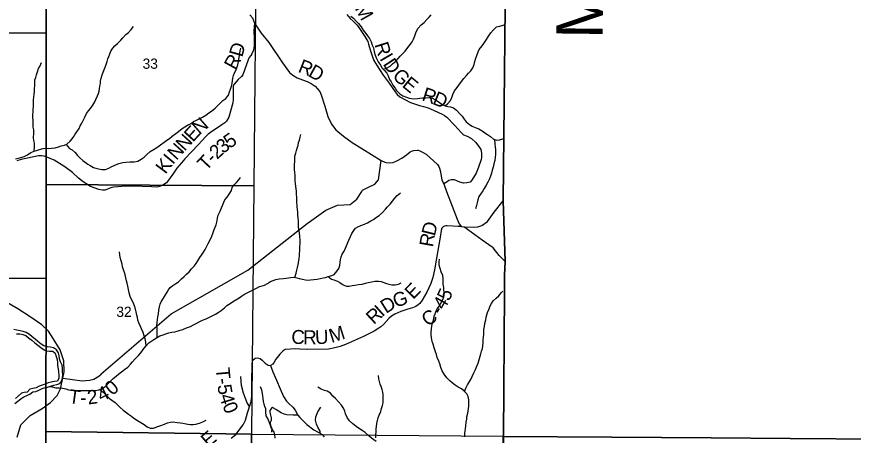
# Model space of a CAD drawing. Extents: x 2043100 to 2470832, y 443715 to 810583.
# Drawn here: x 2290243 to 2308244, y 624120 to 633122 of the extents above; entities that cross this region are included whole.
import ezdxf

# ---------------------------------------------------------------- set-up
doc = ezdxf.new("R2010")
doc.units = 0
for name, color, linetype in [('GM_X_Adjacent_County', 7, 'Continuous'), ('GM_X_Adjacent_County_Text', 7, 'Continuous'), ('GM_X_County', 7, 'Continuous'), ('GM_X_County_Road', 7, 'Continuous'), ('GM_X_County_Road_Text', 7, 'Continuous'), ('GM_X_Major_River', 7, 'Continuous'), ('GM_X_Minor_River', 7, 'Continuous'), ('GM_X_Section', 7, 'Continuous'), ('GM_X_Section_Text', 7, 'Continuous'), ('GM_X_State_Route', 7, 'Continuous'), ('GM_X_Township', 7, 'Continuous'), ('GM_X_Township_Road', 7, 'Continuous'), ('GM_X_Township_Road_Text', 7, 'Continuous'), ('GM_X_Township_ROW', 7, 'Continuous')]:
    doc.layers.add(name, color=color, linetype=linetype)

msp = doc.modelspace()

# ---------------------------------------------------------------- linework, layer by layer
at = {"layer": 'GM_X_Adjacent_County'}
msp.add_lwpolyline([(2310832, 624022), (2306890, 624048), (2305185, 624062), (2303048, 624077), (2300717, 624094), (2300736, 627208), (2300738, 627560), (2300751, 627857), (2300714, 629163), (2300774, 635425)], dxfattribs=at)
at = {"layer": 'GM_X_County'}
msp.add_lwpolyline([(2300774, 635425), (2300714, 629163), (2300751, 627857), (2300738, 627560), (2300736, 627208), (2300717, 624094), (2303048, 624077), (2305185, 624062), (2306890, 624048), (2310832, 624022)], dxfattribs=at)
at = {"layer": 'GM_X_County_Road'}
for points in [[(2295261, 633166), (2295315, 633098), (2295360, 632984), (2295505, 632772), (2295668, 632569), (2295965, 632129), (2296113, 631925), (2296182, 631862), (2296276, 631806), (2296395, 631762), (2296495, 631730), (2296579, 631689), (2296662, 631632), (2296763, 631513), (2296796, 631445), (2296874, 631199), (2296938, 630976), (2297016, 630814), (2297109, 630692), (2297276, 630552), (2297464, 630417), (2298082, 630029), (2298162, 629993), (2298196, 629986), (2298273, 629982), (2298342, 629990), (2298434, 630029), (2298531, 630078), (2298627, 630151), (2298706, 630219), (2298736, 630232), (2298790, 630245), (2298865, 630251), (2298879, 630250), (2298917, 630238), (2298976, 630211), (2299052, 630167), (2299295, 629943), (2299323, 629901), (2299341, 629864), (2299360, 629787), (2299392, 629607), (2299433, 629530), (2299494, 629364), (2299614, 629046), (2299720, 628767), (2299763, 628667), (2299790, 628631), (2299808, 628610), (2299866, 628605), (2300082, 628594), (2300168, 628603), (2300252, 628632), (2300371, 628721), (2300519, 628917), (2300714, 629163)], [(2297345, 633167), (2297418, 633081), (2297482, 633026), (2297535, 632980), (2297571, 632944), (2297608, 632889), (2297731, 632695), (2297776, 632622), (2297797, 632588), (2297815, 632534), (2297848, 632410), (2297898, 632258), (2297929, 632182), (2297998, 632069), (2298126, 631868), (2298255, 631694), (2298385, 631505), (2298428, 631450), (2298488, 631398), (2298716, 631278), (2298908, 631216), (2298996, 631194), (2299097, 631163), (2299225, 631108), (2299400, 631026), (2299450, 630996), (2299499, 630963), (2299666, 630790), (2299745, 630702), (2299804, 630635), (2299860, 630585), (2299937, 630552), (2300029, 630505), (2300120, 630417), (2300201, 630312), (2300230, 630266), (2300246, 630188), (2300241, 630096), (2300234, 630052), (2300179, 629889), (2300127, 629756), (2300040, 629605), (2299997, 629563), (2299931, 629546), (2299855, 629542), (2299777, 629561), (2299728, 629586), (2299662, 629614), (2299598, 629613), (2299540, 629599), (2299506, 629572), (2299433, 629530)], [(2299808, 628610), (2299740, 628607), (2299504, 628623), (2299478, 628625), (2299448, 628614), (2299420, 628600), (2299394, 628574), (2299379, 628527), (2299352, 628383), (2299271, 627889), (2299233, 627681), (2299195, 627510), (2299154, 627383), (2299068, 627194), (2298967, 627023), (2298916, 626954), (2298882, 626922), (2298829, 626890), (2298759, 626859), (2298659, 626832), (2298506, 626782), (2298376, 626727), (2298307, 626684), (2298253, 626634), (2298140, 626509), (2298079, 626452), (2298037, 626420), (2297938, 626359), (2297707, 626242), (2297315, 626070), (2297203, 626031), (2297089, 625998), (2296954, 625973), (2296506, 625961), (2296336, 625969), (2296241, 625982), (2296022, 625962), (2295976, 625938), (2295905, 625867), (2295820, 625758), (2295780, 625690), (2295753, 625651), (2295705, 625623), (2295756, 625481), (2295836, 625304), (2295910, 625116), (2295982, 624956), (2296045, 624855), (2296109, 624795), (2296184, 624726), (2296236, 624658), (2296294, 624550), (2296336, 624505), (2296391, 624443), (2296488, 624352), (2296637, 624237), (2296727, 624188), (2296773, 624165), (2296816, 624138), (2296860, 624089)]]:
    msp.add_lwpolyline(points, dxfattribs=at)
at = {"layer": 'GM_X_Major_River'}
for points in [[(2290200, 624803), (2290269, 624853), (2290333, 624904), (2290396, 624947), (2290462, 624978), (2290523, 625000), (2290589, 625051), (2290656, 625064), (2290708, 625084), (2290776, 625121), (2290837, 625138), (2290905, 625154), (2290973, 625173), (2291041, 625198), (2291104, 625211), (2291168, 625235), (2291214, 625288), (2291231, 625352), (2291236, 625422), (2291225, 625496), (2291226, 625564), (2291220, 625628), (2291187, 625700), (2291164, 625764), (2291160, 625826), (2291143, 625892), (2291100, 625958), (2291038, 626003), (2290972, 626012), (2290902, 626022), (2290830, 626045), (2290767, 626078), (2290697, 626134), (2290640, 626187), (2290576, 626240), (2290515, 626290), (2290449, 626333), (2290385, 626353), (2290315, 626366), (2290248, 626383), (2290184, 626398)], [(2290239, 626299), (2290307, 626302), (2290375, 626288), (2290438, 626267), (2290498, 626212), (2290567, 626162), (2290635, 626111), (2290696, 626057), (2290762, 626008), (2290831, 625955), (2290881, 625939), (2290947, 625930), (2291019, 625931), (2291073, 625889), (2291094, 625817), (2291111, 625749), (2291119, 625681), (2291122, 625617), (2291135, 625551), (2291145, 625483), (2291152, 625411), (2291147, 625347), (2291118, 625285), (2291056, 625276), (2290986, 625261), (2290920, 625249), (2290853, 625222), (2290725, 625177), (2290658, 625142), (2290592, 625123), (2290524, 625110), (2290471, 625048), (2290403, 625043), (2290343, 625026), (2290282, 624970), (2290217, 624909)]]:
    msp.add_lwpolyline(points, dxfattribs=at)
at = {"layer": 'GM_X_Minor_River'}
for points in [[(2297436, 633135), (2297488, 633090), (2297548, 633026), (2297601, 632980), (2297655, 632908), (2297697, 632835), (2297758, 632763), (2297792, 632711), (2297835, 632651), (2297867, 632579), (2297894, 632514), (2297918, 632452), (2297938, 632368), (2297955, 632298), (2297987, 632226), (2298022, 632152), (2298068, 632080), (2298105, 632016), (2298155, 631969), (2298205, 631907), (2298234, 631849), (2298266, 631773), (2298299, 631719), (2298335, 631653), (2298384, 631584), (2298416, 631532), (2298486, 631466), (2298555, 631418), (2298627, 631389), (2298687, 631373), (2298739, 631364), (2298801, 631356), (2298867, 631362), (2298921, 631373), (2298976, 631379), (2299044, 631380), (2299120, 631384), (2299190, 631371), (2299241, 631341), (2299291, 631313), (2299341, 631279), (2299393, 631244), (2299461, 631204), (2299517, 631192), (2299577, 631187), (2299645, 631161), (2299706, 631112), (2299778, 631036), (2299828, 630984), (2299875, 630922), (2299917, 630861), (2299984, 630803), (2300042, 630767), (2300110, 630740), (2300190, 630714), (2300262, 630669), (2300315, 630627), (2300377, 630589), (2300435, 630544), (2300505, 630490), (2300571, 630464), (2300635, 630473), (2300703, 630497), (2300731, 630506)], [(2298130, 631993), (2298203, 632019), (2298276, 632061), (2298328, 632110), (2298399, 632168), (2298451, 632221), (2298493, 632271), (2298542, 632322), (2298602, 632380), (2298657, 632460), (2298715, 632531), (2298750, 632585), (2298780, 632639), (2298811, 632710), (2298841, 632794), (2298884, 632874), (2298946, 632949), (2299011, 632997), (2299069, 633060), (2299116, 633112), (2299162, 633162)], [(2299465, 631203), (2299519, 631259), (2299574, 631319), (2299604, 631383), (2299627, 631451), (2299663, 631526), (2299718, 631600), (2299756, 631651), (2299815, 631727), (2299867, 631795), (2299922, 631856), (2299966, 631910), (2300018, 631961), (2300061, 632021), (2300089, 632097), (2300104, 632157), (2300122, 632228), (2300141, 632286), (2300175, 632364), (2300196, 632414), (2300258, 632495), (2300297, 632549), (2300351, 632632), (2300398, 632702), (2300445, 632776), (2300505, 632843), (2300570, 632903), (2300642, 632920), (2300712, 632942), (2300755, 632952)], [(2290219, 630064), (2290275, 630082), (2290329, 630096), (2290403, 630117), (2290475, 630153), (2290546, 630202), (2290618, 630232), (2290672, 630245), (2290732, 630263), (2290809, 630286), (2290873, 630292), (2290935, 630290), (2290995, 630293), (2291067, 630305), (2291143, 630326), (2291203, 630342), (2291268, 630363), (2291320, 630381), (2291396, 630444), (2291437, 630496), (2291469, 630546), (2291499, 630598), (2291534, 630649), (2291586, 630721), (2291609, 630775), (2291645, 630832), (2291682, 630906), (2291708, 630962), (2291743, 631038), (2291787, 631097), (2291828, 631151), (2291878, 631218), (2291925, 631290), (2291947, 631342), (2291978, 631418), (2292000, 631469), (2292020, 631521), (2292025, 631573), (2292035, 631627), (2292045, 631683), (2292048, 631733), (2292060, 631799), (2292083, 631870), (2292116, 631964), (2292148, 632036), (2292170, 632096), (2292191, 632159), (2292205, 632215), (2292222, 632269), (2292248, 632325), (2292277, 632395), (2292311, 632448), (2292357, 632498), (2292412, 632543), (2292486, 632619), (2292523, 632671), (2292591, 632740), (2292650, 632784), (2292708, 632845), (2292757, 632909)], [(2291307, 630376), (2291381, 630289), (2291435, 630256), (2291503, 630204), (2291548, 630138), (2291598, 630090), (2291668, 630027), (2291773, 629951), (2291825, 629922), (2291897, 629880), (2291949, 629862), (2292003, 629851), (2292075, 629837), (2292155, 629838), (2292223, 629862), (2292279, 629890), (2292356, 629931), (2292444, 629966), (2292524, 629984), (2292592, 629997), (2292680, 630001), (2292772, 630004), (2292849, 630012), (2292919, 630057), (2292987, 630103), (2293042, 630156), (2293116, 630224), (2293203, 630275), (2293281, 630321), (2293335, 630366), (2293414, 630424), (2293472, 630467), (2293529, 630505), (2293591, 630554), (2293669, 630612), (2293722, 630653), (2293804, 630719), (2293859, 630756), (2293915, 630788), (2293995, 630827), (2294046, 630865), (2294098, 630893), (2294166, 630924), (2294242, 630964), (2294311, 631005), (2294377, 631053), (2294436, 631092), (2294510, 631158), (2294579, 631217), (2294627, 631273), (2294679, 631318), (2294746, 631364), (2294800, 631434), (2294823, 631505), (2294843, 631567), (2294864, 631629), (2294876, 631689), (2294885, 631751), (2294891, 631803), (2294905, 631860), (2294932, 631912), (2294958, 631962), (2294982, 632020), (2294999, 632090), (2295015, 632161), (2295022, 632211), (2295034, 632285), (2295043, 632341), (2295053, 632391), (2295067, 632443)], [(2290618, 630232), (2290627, 630326), (2290627, 630399), (2290614, 630461), (2290602, 630515), (2290609, 630619), (2290609, 630687), (2290598, 630749), (2290594, 630821), (2290595, 630897), (2290593, 630951), (2290592, 631013), (2290596, 631067), (2290600, 631137), (2290603, 631187), (2290603, 631265), (2290604, 631334), (2290608, 631392), (2290617, 631446), (2290623, 631514), (2290629, 631580), (2290630, 631634), (2290632, 631700), (2290635, 631762), (2290651, 631814), (2290672, 631869), (2290690, 631937), (2290715, 632009), (2290747, 632065), (2290775, 632136)], [(2296226, 627514), (2296255, 627603), (2296273, 627669), (2296286, 627725), (2296302, 627796), (2296317, 627870), (2296323, 627920), (2296329, 627978), (2296330, 628030), (2296334, 628090), (2296337, 628166), (2296343, 628250), (2296346, 628323), (2296334, 628397), (2296325, 628471), (2296317, 628535), (2296310, 628617), (2296308, 628669), (2296303, 628731), (2296299, 628791), (2296294, 628857), (2296290, 628917), (2296286, 628973), (2296281, 629031), (2296268, 629163), (2296268, 629233), (2296263, 629305), (2296261, 629367), (2296255, 629421), (2296248, 629473), (2296240, 629533), (2296235, 629595), (2296233, 629659), (2296232, 629716), (2296228, 629772), (2296222, 629838), (2296217, 629892), (2296217, 629952), (2296226, 630002), (2296230, 630060), (2296230, 630126), (2296249, 630186), (2296267, 630244), (2296280, 630297), (2296298, 630351), (2296308, 630417), (2296325, 630469), (2296341, 630531), (2296360, 630587)], [(2300526, 630482), (2300534, 630390), (2300537, 630318), (2300543, 630268), (2300547, 630214), (2300546, 630156), (2300540, 630104), (2300531, 630028), (2300513, 629955), (2300498, 629885), (2300476, 629823), (2300457, 629757), (2300437, 629693), (2300415, 629634), (2300382, 629562), (2300344, 629496), (2300301, 629427), (2300273, 629377), (2300226, 629305), (2300190, 629252), (2300165, 629186), (2300151, 629116), (2300138, 629062), (2300118, 628992)], [(2293268, 626227), (2293267, 626310), (2293267, 626366), (2293264, 626422), (2293260, 626475), (2293263, 626555), (2293269, 626605), (2293278, 626665), (2293292, 626735), (2293303, 626807), (2293319, 626883), (2293332, 626940), (2293354, 626992), (2293403, 627070), (2293443, 627139), (2293479, 627195), (2293508, 627245), (2293548, 627295), (2293599, 627340), (2293669, 627384), (2293721, 627423), (2293788, 627483), (2293844, 627532), (2293899, 627584), (2293953, 627638), (2294003, 627701), (2294064, 627759), (2294108, 627816), (2294137, 627868), (2294183, 627942), (2294220, 627997), (2294260, 628057), (2294295, 628117), (2294329, 628175), (2294360, 628242), (2294400, 628310), (2294439, 628404), (2294463, 628463), (2294488, 628525), (2294516, 628597), (2294533, 628649), (2294547, 628706), (2294560, 628786), (2294578, 628854), (2294619, 628942), (2294649, 629009), (2294670, 629059), (2294702, 629135), (2294724, 629185), (2294769, 629238), (2294817, 629308), (2294862, 629384), (2294882, 629447), (2294925, 629505), (2294969, 629555), (2295026, 629612), (2295058, 629662)], [(2297205, 627841), (2297208, 627894), (2297228, 627960), (2297245, 628014), (2297291, 628080), (2297321, 628143), (2297342, 628195), (2297366, 628265), (2297391, 628315), (2297425, 628392), (2297452, 628458), (2297494, 628522), (2297531, 628574), (2297585, 628605), (2297647, 628633), (2297727, 628658), (2297790, 628686), (2297864, 628729), (2297918, 628763), (2297987, 628808), (2298043, 628848), (2298114, 628909), (2298182, 628981), (2298219, 629033), (2298281, 629094), (2298327, 629152), (2298376, 629217), (2298428, 629275), (2298501, 629336)], [(2293027, 626046), (2293024, 626125), (2293010, 626195), (2292987, 626261), (2292963, 626328), (2292929, 626406), (2292908, 626460), (2292874, 626538), (2292851, 626592), (2292839, 626650), (2292825, 626706), (2292812, 626776), (2292800, 626830), (2292777, 626902), (2292749, 626978), (2292714, 627038), (2292684, 627102), (2292661, 627182), (2292649, 627258), (2292636, 627324), (2292620, 627388), (2292606, 627440), (2292589, 627508), (2292579, 627568), (2292560, 627622), (2292542, 627681), (2292522, 627745), (2292509, 627801), (2292489, 627873), (2292470, 627943), (2292460, 627999), (2292457, 628065)], [(2299883, 624086), (2299888, 624156), (2299896, 624206), (2299901, 624262), (2299909, 624318), (2299918, 624398), (2299926, 624466), (2299932, 624517), (2299949, 624593), (2299959, 624643), (2299968, 624697), (2299974, 624747), (2299973, 624885), (2299960, 624951), (2299932, 625009), (2299874, 625069), (2299817, 625117), (2299745, 625156), (2299675, 625198), (2299615, 625249), (2299562, 625293), (2299500, 625357), (2299442, 625431), (2299401, 625504), (2299369, 625576), (2299346, 625654), (2299328, 625714), (2299293, 625794), (2299273, 625858), (2299256, 625912), (2299228, 625998), (2299203, 626076), (2299183, 626136), (2299170, 626224), (2299164, 626274), (2299162, 626336), (2299165, 626404), (2299177, 626476), (2299190, 626534), (2299208, 626597), (2299227, 626681), (2299245, 626731), (2299266, 626793), (2299298, 626844), (2299331, 626898), (2299365, 626950), (2299397, 627012), (2299424, 627073), (2299440, 627129), (2299439, 627191), (2299435, 627245), (2299433, 627295), (2299422, 627367), (2299422, 627433), (2299419, 627489), (2299409, 627555), (2299380, 627633), (2299356, 627705), (2299337, 627775), (2299333, 627847), (2299344, 627909)], [(2290945, 625165), (2291007, 625162), (2291087, 625143), (2291167, 625137), (2291229, 625134), (2291299, 625116), (2291355, 625099), (2291405, 625091), (2291475, 625083), (2291543, 625080), (2291597, 625080), (2291671, 625079), (2291733, 625083), (2291807, 625081), (2291885, 625080), (2291949, 625082), (2292007, 625095), (2292088, 625123), (2292144, 625170), (2292205, 625226), (2292259, 625281), (2292321, 625337), (2292382, 625392), (2292440, 625444), (2292497, 625486), (2292565, 625537), (2292635, 625581), (2292694, 625650), (2292736, 625702), (2292791, 625763), (2292865, 625833), (2292916, 625894), (2292964, 625964), (2293019, 626038), (2293086, 626105), (2293190, 626182), (2293248, 626216), (2293325, 626257), (2293391, 626283), (2293451, 626302), (2293519, 626320), (2293578, 626334), (2293644, 626347), (2293696, 626359), (2293758, 626380), (2293818, 626398), (2293899, 626433), (2293979, 626461), (2294045, 626494), (2294101, 626524), (2294172, 626562), (2294240, 626593), (2294322, 626623), (2294407, 626664), (2294463, 626694), (2294517, 626725), (2294581, 626763), (2294640, 626804), (2294714, 626858), (2294763, 626909), (2294833, 626957), (2294887, 626990), (2294958, 627036), (2295028, 627079), (2295080, 627113), (2295145, 627155), (2295203, 627182), (2295289, 627224), (2295346, 627257), (2295402, 627285), (2295466, 627316), (2295522, 627332), (2295578, 627350), (2295637, 627385), (2295707, 627429), (2295765, 627452), (2295817, 627468), (2295888, 627485), (2295986, 627489), (2296040, 627500), (2296092, 627508), (2296144, 627510), (2296204, 627517), (2296272, 627507), (2296322, 627491), (2296394, 627476), (2296454, 627462), (2296512, 627457), (2296568, 627461), (2296640, 627467), (2296708, 627480), (2296770, 627488), (2296835, 627503), (2296887, 627515), (2296947, 627531), (2297021, 627556), (2297075, 627580), (2297140, 627653), (2297174, 627705), (2297197, 627771), (2297205, 627841)], [(2296948, 627532), (2297015, 627474), (2297069, 627460), (2297144, 627435), (2297194, 627409), (2297268, 627355), (2297342, 627330), (2297400, 627330), (2297464, 627338), (2297518, 627349), (2297598, 627359), (2297676, 627372), (2297749, 627390), (2297809, 627405), (2297883, 627421), (2297949, 627434), (2298029, 627432), (2298083, 627429), (2298143, 627407), (2298197, 627385), (2298251, 627372), (2298315, 627358), (2298387, 627356), (2298455, 627367), (2298517, 627395)], [(2299880, 625062), (2299909, 625135), (2299945, 625202), (2299982, 625260), (2300022, 625330), (2300047, 625384), (2300083, 625461), (2300114, 625531), (2300144, 625603), (2300175, 625672), (2300203, 625768), (2300214, 625818), (2300228, 625874), (2300247, 625930), (2300263, 625983), (2300273, 626035), (2300280, 626113), (2300282, 626163), (2300289, 626237), (2300295, 626287), (2300295, 626337), (2300296, 626391), (2300308, 626462), (2300319, 626524), (2300339, 626604), (2300348, 626658), (2300360, 626708), (2300373, 626760), (2300407, 626841), (2300430, 626903), (2300458, 626957), (2300496, 627010), (2300559, 627070), (2300615, 627118), (2300674, 627189), (2300700, 627218)], [(2297968, 624063), (2297972, 624127), (2297976, 624190), (2297979, 624256), (2297985, 624310), (2297994, 624372), (2298010, 624440), (2298019, 624494), (2298041, 624554), (2298076, 624631), (2298094, 624697), (2298111, 624761), (2298125, 624819), (2298131, 624871), (2298132, 624946), (2298132, 624996), (2298119, 625048), (2298105, 625102), (2298085, 625166), (2298066, 625222), (2298048, 625273), (2298034, 625331), (2298025, 625402)], [(2292030, 625103), (2292103, 625045), (2292169, 624982), (2292240, 624912), (2292290, 624876), (2292360, 624823), (2292418, 624765), (2292469, 624719), (2292537, 624662), (2292587, 624622), (2292646, 624576), (2292712, 624530), (2292766, 624489), (2292842, 624437), (2292917, 624396), (2292985, 624354), (2293049, 624300), (2293115, 624271), (2293185, 624271), (2293277, 624308), (2293347, 624328), (2293420, 624355), (2293488, 624385), (2293554, 624404), (2293606, 624406), (2293694, 624397), (2293764, 624387), (2293818, 624377), (2293924, 624358), (2293982, 624350), (2294040, 624349), (2294100, 624359), (2294176, 624378), (2294245, 624410), (2294317, 624447)], [(2295806, 624058), (2295794, 624130), (2295783, 624186), (2295729, 624267), (2295701, 624331), (2295672, 624407), (2295644, 624479), (2295613, 624537), (2295605, 624617), (2295604, 624685), (2295580, 624739), (2295565, 624791), (2295555, 624845), (2295543, 624913), (2295536, 624965), (2295530, 625021), (2295515, 625087), (2295487, 625161)], [(2297976, 623982), (2297879, 624057), (2297818, 624110), (2297740, 624178), (2297678, 624224), (2297619, 624259), (2297549, 624307), (2297473, 624367), (2297402, 624430), (2297356, 624502), (2297321, 624580), (2297303, 624636), (2297277, 624704), (2297232, 624766), (2297170, 624841), (2297101, 624911), (2297047, 624961), (2296993, 625026), (2296924, 625070), (2296866, 625086), (2296792, 625111), (2296724, 625157)]]:
    msp.add_lwpolyline(points, dxfattribs=at)
at = {"layer": 'GM_X_Section'}
for points in [[(2290879, 638197), (2290879, 634870), (2290879, 632765), (2285560, 632813), (2285590, 638254)], [(2295397, 634855), (2295344, 629488), (2290878, 629512), (2290879, 632765), (2290879, 634870)], [(2290879, 632765), (2290878, 629512), (2290876, 627501), (2285548, 627483), (2285560, 632813)], [(2290878, 629512), (2295344, 629488), (2295292, 624145), (2290870, 624199), (2290876, 627501)], [(2290876, 627501), (2290870, 624199), (2290863, 622088), (2285518, 622176), (2285548, 627483)], [(2295292, 624145), (2295311, 618781), (2290868, 618859), (2290863, 622088), (2290870, 624199)], [(2300703, 624098), (2300644, 618693), (2295585, 618781), (2295311, 618781), (2295292, 624145)]]:
    msp.add_lwpolyline(points, close=True, dxfattribs=at)
at = {"layer": 'GM_X_State_Route'}
msp.add_lwpolyline([(2290250, 624081), (2290335, 624342), (2290531, 624544), (2290788, 624696), (2290972, 624824), (2291113, 624975), (2291187, 625115), (2291223, 625285), (2291237, 625351), (2291265, 625486), (2291256, 625717), (2291175, 625954), (2291026, 626201), (2290924, 626358), (2290787, 626494), (2290535, 626665), (2290264, 626840), (2289944, 627024)], dxfattribs=at)
at = {"layer": 'GM_X_Township'}
msp.add_lwpolyline([(2300774, 635425), (2300714, 629163), (2300751, 627857), (2300738, 627560), (2300736, 627208), (2300717, 624094), (2300679, 619574), (2300671, 618691), (2297254, 618753), (2291836, 618850), (2290900, 618867), (2290876, 619364), (2290886, 622083), (2282304, 622194), (2280174, 622203), (2280172, 624926), (2280171, 625972), (2280171, 626273), (2280217, 630381), (2280231, 632865), (2275787, 632915), (2274911, 632948), (2274969, 638401)], dxfattribs=at)
at = {"layer": 'GM_X_Township_Road'}
for points in [[(2295360, 632984), (2295349, 632909), (2295345, 632810), (2295349, 632664), (2295355, 632558), (2295352, 632498), (2295336, 632406), (2295305, 632321), (2295278, 632286), (2295248, 632246), (2295227, 632195), (2295109, 631873), (2295077, 631834), (2295006, 631775), (2294920, 631675), (2294903, 631641), (2294898, 631555), (2294898, 631343), (2294891, 631270), (2294804, 630960), (2294754, 630875), (2294721, 630841), (2294655, 630794), (2294414, 630633), (2294361, 630598), (2294310, 630545), (2294147, 630364), (2293864, 630065), (2293791, 629980), (2293691, 629868), (2293600, 629738), (2293488, 629578), (2293463, 629546), (2293407, 629513), (2293336, 629478), (2293290, 629465), (2293248, 629458), (2293150, 629461), (2293149, 629461)], [(2293149, 629461), (2292730, 629475), (2292506, 629474), (2292336, 629459), (2292293, 629452), (2292247, 629435), (2292185, 629404), (2292142, 629394), (2292088, 629389), (2292007, 629409), (2291834, 629471), (2291675, 629568), (2291573, 629649), (2291441, 629771), (2291279, 629894), (2291050, 630036), (2290877, 630112), (2290833, 630123), (2290775, 630132), (2290709, 630129), (2290342, 630053), (2290243, 630023)], [(2297670, 629363), (2297686, 629388), (2297812, 629458), (2297947, 629518), (2298028, 629616), (2298056, 629821), (2298082, 630029)], [(2294860, 624056), (2294958, 624139), (2295117, 624346), (2295165, 624447), (2295210, 624602), (2295237, 624689), (2295254, 624735), (2295261, 624755), (2295290, 624844), (2295300, 624952), (2295301, 625263), (2295312, 625658), (2295319, 625716), (2295328, 625740), (2295376, 625779), (2295426, 625784), (2295482, 625769), (2295527, 625734), (2295586, 625670), (2295630, 625639), (2295656, 625628), (2295705, 625623)], [(2291237, 625351), (2291654, 625293), (2291808, 625303), (2291906, 625325), (2292007, 625393), (2292059, 625437)], [(2295254, 624735), (2295202, 624815), (2295165, 624912), (2295125, 625024), (2295080, 625193), (2295063, 625381)], [(2296294, 624550), (2296193, 624551), (2296055, 624560), (2296001, 624573), (2295930, 624604), (2295821, 624675), (2295772, 624702), (2295746, 624715), (2295724, 624705), (2295711, 624679), (2295691, 624654), (2295688, 624620), (2295696, 624580), (2295713, 624523), (2295718, 624491), (2295717, 624438), (2295698, 624396), (2295694, 624384), (2295707, 624332), (2295730, 624268), (2295723, 624184)], [(2296773, 624165), (2296771, 624209), (2296723, 624295), (2296692, 624358), (2296671, 624444), (2296678, 624513), (2296720, 624621), (2296786, 624727)]]:
    msp.add_lwpolyline(points, dxfattribs=at)
at = {"layer": 'GM_X_Township_ROW'}
for points in [[(2292059, 625437), (2292059, 625438), (2293567, 626731), (2295213, 627670), (2296494, 628671), (2296893, 628958), (2297149, 629066), (2297421, 629083), (2297565, 629197), (2297669, 629362), (2297670, 629363)], [(2300744, 627864), (2300631, 627979), (2300626, 627988), (2300497, 628154), (2300405, 628217), (2300258, 628317), (2299866, 628605)], [(2300738, 627551), (2300738, 627560), (2300751, 627857), (2300744, 627864)], [(2301026, 621740), (2301005, 621745), (2300911, 621939), (2300767, 622163), (2300747, 622325), (2300717, 624094), (2300736, 627208), (2300738, 627551)]]:
    msp.add_lwpolyline(points, dxfattribs=at)

# ---------------------------------------------------------------- texts
at = {"layer": 'GM_X_Adjacent_County_Text'}
msp.add_text('MONROE COUNTY', height=1000, rotation=89.2939, dxfattribs=at).set_placement((2302851, 632641))
at = {"layer": 'GM_X_County_Road_Text'}
for s, rotation, p in [('M', 299.5789, (2297509, 633300)), ('R', 287.5722, (2297938, 632525)), ('R', 338.4631, (2296278, 631940)), ('I', 300.2267, (2298042, 632224)), ('D', 303.292, (2298113, 632103)), ('D', 330.7476, (2296497, 631854)), ('G', 317.2518, (2298309, 631822)), ('E', 320.7227, (2298518, 631629)), ('R', 341.649, (2298943, 631328)), ('D', 337.2123, (2299171, 631253)), ('D', 75.9779, (2299239, 628391)), ('R', 80.3413, (2299199, 628155)), ('E', 46.0061, (2298775, 627028)), ('G', 18.7851, (2298395, 626860)), ('5', 65.9917, (2299547, 626988)), ('D', 31.9753, (2298188, 626728)), ('4', 60.2671, (2299441, 626798)), ('R', 42.8054, (2297928, 626487)), ('I', 42.2558, (2298108, 626654)), ('C', 36.6076, (2299092, 626445)), ('-', 59.5293, (2299376, 626688)), ('M', 17.2987, (2297016, 626103)), ('C', 357.3647, (2296147, 626091)), ('R', 359.7075, (2296407, 626079)), ('U', 2.3089, (2296668, 626078))]:
    msp.add_text(s, height=300, rotation=rotation, dxfattribs=at).set_placement(p)
at = {"layer": 'GM_X_Section_Text'}
for s, p in [('33', (2292952, 632002)), ('32', (2292387, 626665))]:
    msp.add_text(s, height=220.8, rotation=0, dxfattribs=at).set_placement(p)
at = {"layer": 'GM_X_Township_Road_Text'}
for s, rotation, p in [('D', 74.0517, (2295095, 632239)), ('R', 61.3294, (2294950, 631957)), ('N', 41.1695, (2294178, 630570)), ('E', 47.4706, (2294033, 630411)), ('N', 47.5509, (2293855, 630216)), ('5', 34.8837, (2294825, 630277)), ('N', 47.9094, (2293678, 630020)), ('3', 39.4644, (2294687, 630164)), ('2', 43.1635, (2294556, 630041)), ('K', 53.2219, (2293445, 629720)), ('I', 50.0405, (2293601, 629928)), ('T', 46.7761, (2294320, 629792)), ('-', 45.8335, (2294473, 629955)), ('T', 274.9259, (2294525, 625563)), ('4', 25.6908, (2292062, 624834)), ('0', 40.727, (2292300, 624961)), ('5', 279.228, (2294560, 625192)), ('-', 275.5856, (2294545, 625336)), ('T', 352.042, (2291346, 624815)), ('2', 7.5604, (2291780, 624780)), ('-', 358.5039, (2291605, 624781)), ('4', 287.0521, (2294599, 624966)), ('0', 292.1966, (2294664, 624762)), ('E', 40.9206, (2294368, 623846))]:
    msp.add_text(s, height=300, rotation=rotation, dxfattribs=at).set_placement(p)

doc.saveas('drawing.dxf')
